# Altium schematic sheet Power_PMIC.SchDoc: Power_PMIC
size A3; CompanyName: STMicroelectronics; Organization: Microcontrollers Division; Address1: 12, Rue Jules HOROWITZ; Address2: 38019 Grenoble; Address3: FRANCE; SheetNumber: 5; SheetTotal: 7
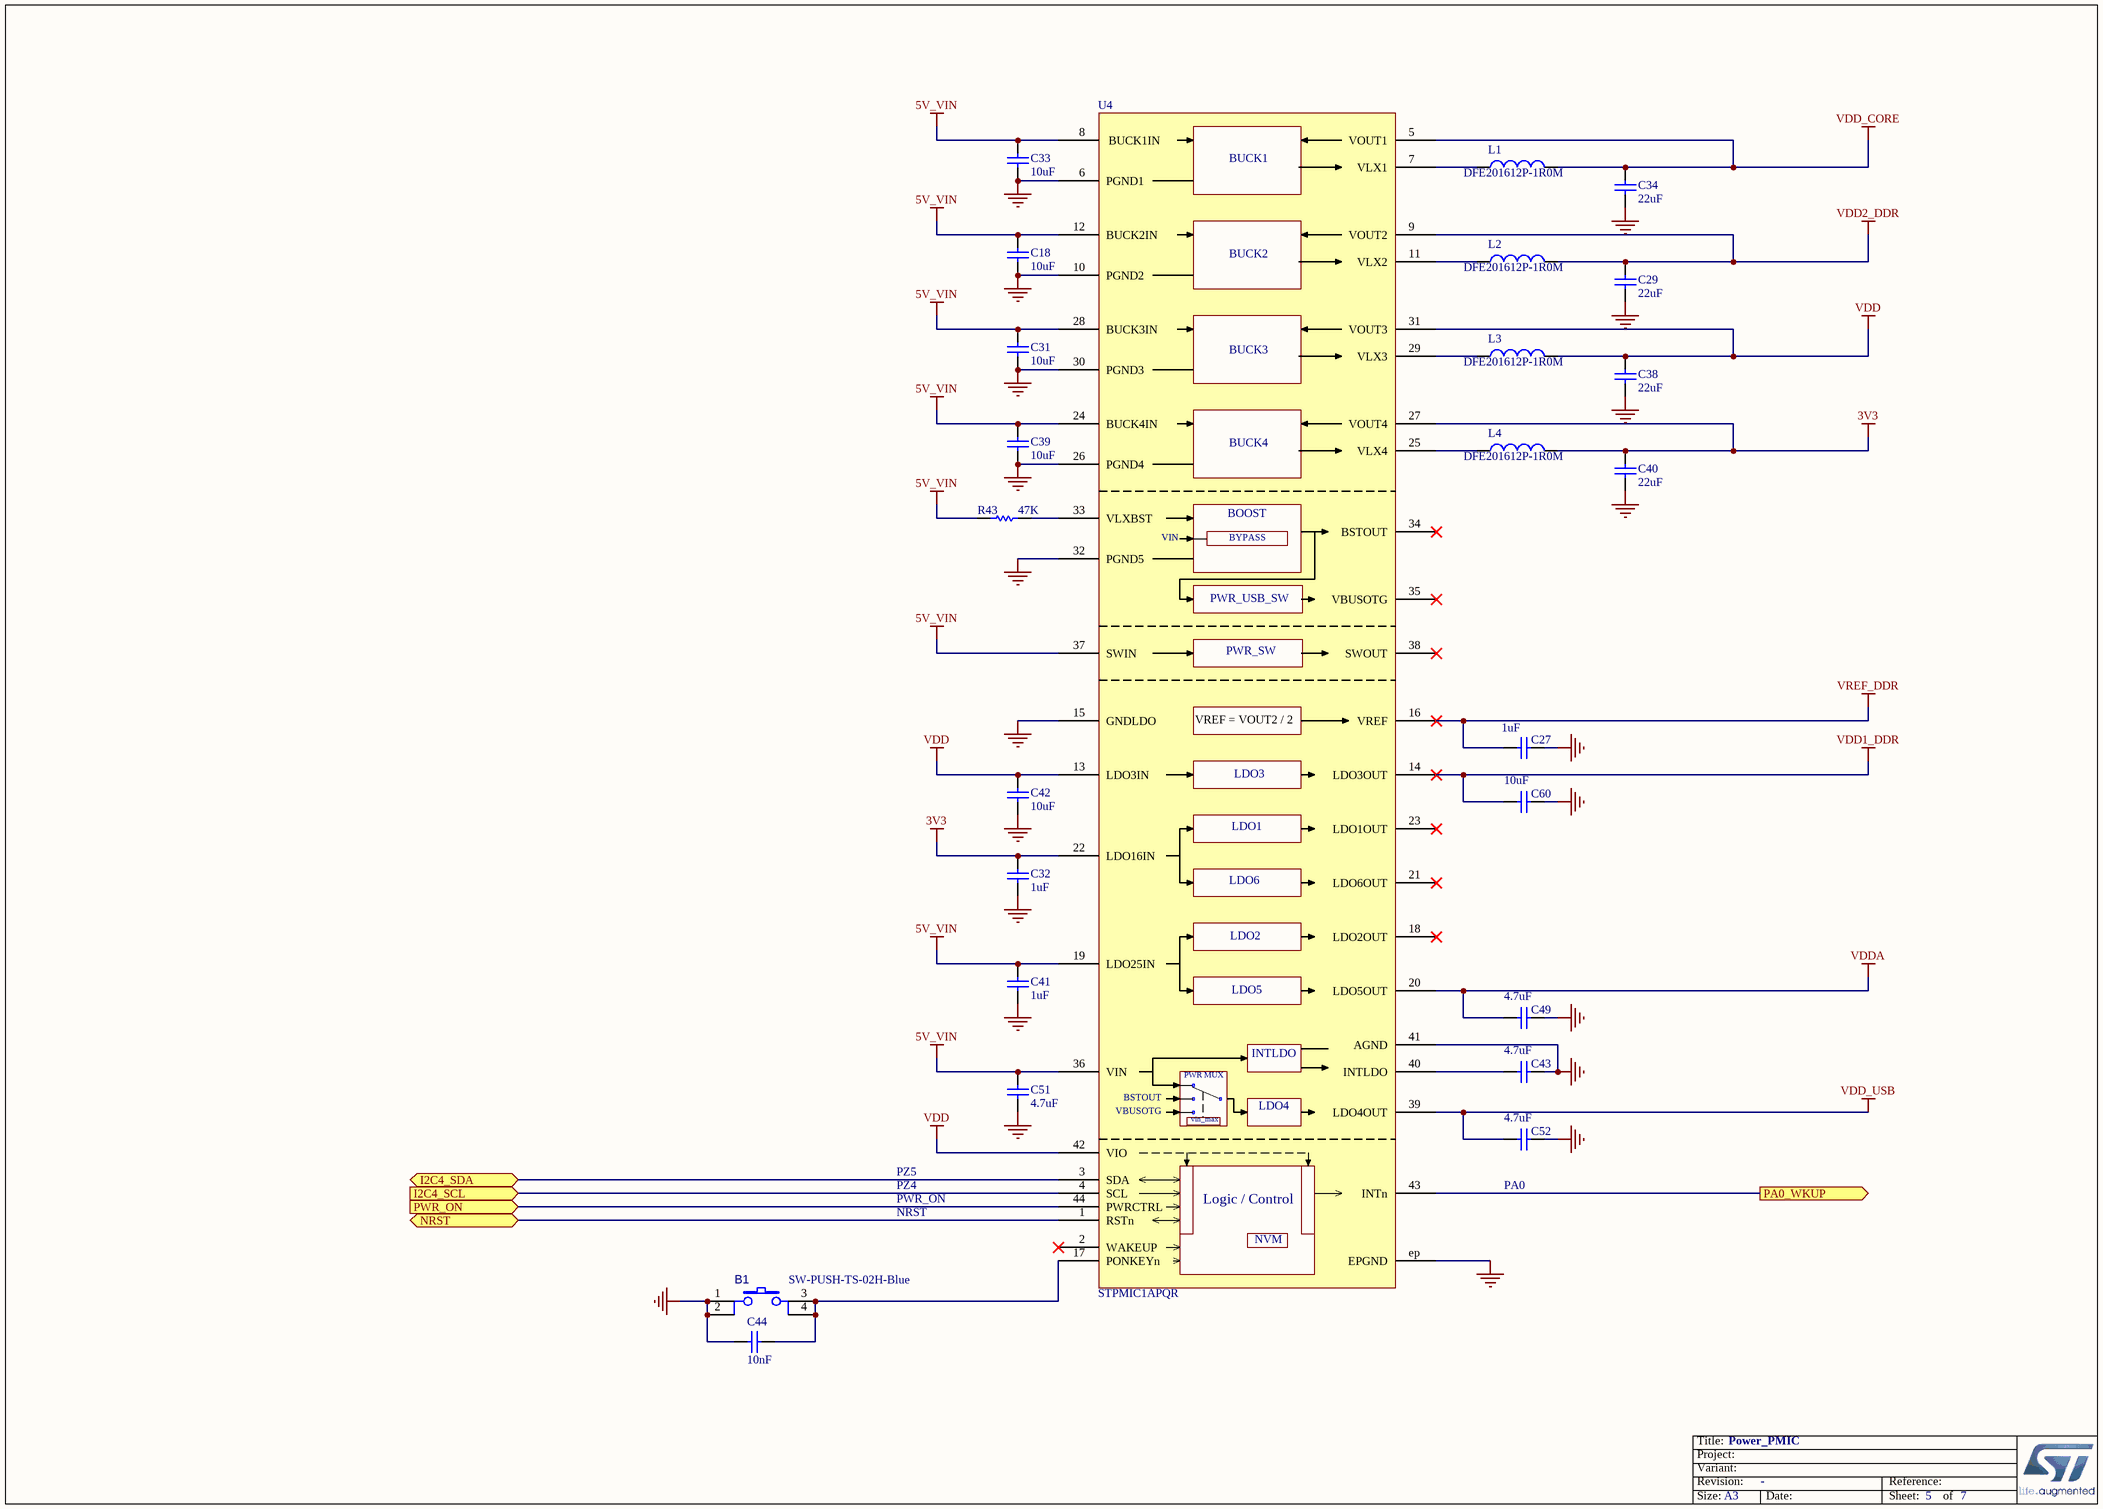
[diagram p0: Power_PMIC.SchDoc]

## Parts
B1  value SW-PUSH-TS-02H-Blue  [SWI_JIUBABA_C-TS-02H-2-5-B-V-T_R_BLUE]
C18  value 10uF  [C0603]
C27  value 1uF  [C0402]
C29  value 22uF  [C0603]
C31  value 10uF  [C0603]
C32  value 1uF  [C0402]
C33  value 10uF  [C0603]
C34  value 22uF  [C0603]
C38  value 22uF  [C0603]
C39  value 10uF  [C0603]
C40  value 22uF  [C0603]
C41  value 1uF  [C0402]
C42  value 10uF  [C0603]
C43  value 4.7uF  [C0402]
C44  value 10nF  [C0402]
C49  value 4.7uF  [C0402]
C51  value 4.7uF  [C0402]
C52  value 4.7uF  [C0402]
C60  value 10uF  [C0603]
L1  value DFE201612P-1R0M  [IND_MURATA_DFE201612P]
L2  value DFE201612P-1R0M  [IND_MURATA_DFE201612P]
L3  value DFE201612P-1R0M  [IND_MURATA_DFE201612P]
L4  value DFE201612P-1R0M  [IND_MURATA_DFE201612P]
R43  value 47K  [R0402]
U4  value STPMIC1APQR  [ICC_WFQFN44-EPAD_5X6_P040]

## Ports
I2C4_SCL (in), I2C4_SDA (bidir), NRST (bidir), PA0_WKUP (out), PWR_ON (in)

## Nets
3V3: C32.2 C40.2 L4.2 U4.22(LDO16IN) U4.27(VOUT4)
5V_VIN: C18.2 C31.2 C33.2 C39.2 C41.2 C51.1 R43.2 U4.8(BUCK1IN) U4.12(BUCK2IN) U4.19(LDO25IN) U4.24(BUCK4IN) U4.28(BUCK3IN) U4.36(VIN) U4.37(SWIN)
GND: B1.1 B1.2 C18.1 C27.1 C29.1 C31.1 C32.1 C33.1 C34.1 C38.1 C39.1 C40.1 C41.1 C42.1 C43.1 C44.1 C49.1 C51.2 C52.1 C60.1 U4.6(PGND1) U4.10(PGND2) U4.15(GNDLDO) U4.26(PGND4) U4.30(PGND3) U4.32(PGND5) U4.41(AGND) U4.ep(EPGND)
VDD: C38.2 C42.2 L3.2 U4.13(LDO3IN) U4.31(VOUT3) U4.42(VIO)
VDD1_DDR: C60.2 U4.14(LDO3OUT)
VDD2_DDR: C29.2 L2.2 U4.9(VOUT2)
VDD_CORE: C34.2 L1.2 U4.5(VOUT1)
VDD_USB: C52.2 U4.39(LDO4OUT)
VDDA: C49.2 U4.20(LDO5OUT)
VREF_DDR: C27.2 U4.16(VREF)
I2C4_SCL: U4.4(SCL) ; port I2C4_SCL
I2C4_SDA: U4.3(SDA) ; port I2C4_SDA
NRST: U4.1(RSTn) ; port NRST
PA0_WKUP: U4.43(INTn) ; port PA0_WKUP
PWR_ON: U4.44(PWRCTRL) ; port PWR_ON
NetB1_3: B1.3 B1.4 C44.2 U4.17(PONKEYn)
NetC43_2: C43.2 U4.40(INTLDO)
NetL1_1: L1.1 U4.7(VLX1)
NetL2_1: L2.1 U4.11(VLX2)
NetL3_1: L3.1 U4.29(VLX3)
NetL4_1: L4.1 U4.25(VLX4)
NetR43_1: R43.1 U4.33(VLXBST)

Not connected (* = marked no-connect by the designer): U4 2(WAKEUP)* 18(LDO2OUT)* 21(LDO6OUT)* 23(LDO1OUT)* 34(BSTOUT)* 35(VBUSOTG)* 38(SWOUT)*

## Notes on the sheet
- PZ5
- PZ4
- (near C52) PA0
- PWR_ON
- NRST

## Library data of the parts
B1 = MCD-00172: Switch HW SMD blue; Part_Type: Misc; Manufacturer_Part_Number: C-TS-02H-2.5-B-V-T/R BLUE; Manufacturer: JIUBABA; Provided_By: SUBCO
C18 C31 C33 C39 C42 C60 = MCD-00099: Capacitor, MLCC, 10uF, 10V, X5R, 10%, 0603, T=0,8mm; Manufacturer_Part_Number: GRM188R61A106KE69D; Manufacturer: MURATA; Provided_By: SUBCO; ECCN_US: EAR99; ECCN_EU: NEC
C27 C32 C41 = MCD-00095: Capacitor, MLCC, 1uF, 25V, X5R, 10%, 0402, T=0,5mm; Manufacturer_Part_Number: GRM155R61E105KA12; Manufacturer: MURATA; Alternate_Manufacturer_Part_Number: GRM155R60J105KE19; Provided_By: SUBCO; ECCN_US: EAR99; ECCN_EU: NEC
C29 C34 C38 C40 = MCD-00100: Capacitor, MLCC, 22uF, 6V3, X5R, 20%, 0603, T=0,8mm; Manufacturer_Part_Number: GRM188R60J226MEA0J; Manufacturer: MURATA; Provided_By: SUBCO; ECCN_US: EAR99; ECCN_EU: NEC
C43 C49 C51 C52 = MCD-01356: Capacitor, MLCC, 4.7uF, 6V3, X5R, 20%, 0402, T=0,5mm; Manufacturer_Part_Number: GRM155R60J475ME47; Manufacturer: MURATA; Alternate_Manufacturer_Part_Number: GRM155R60J475ME87; Provided_By: SUBCO; ECCN_US: EAR99; ECCN_EU: NEC
C44 = MCD-00011: Capacitor, MLCC, 10nF, 16V, X7R, 10%, 0402, T=0.5mm; Manufacturer_Part_Number: CC0402KRX7R7BB103; Manufacturer: YAGEO; Provided_By: SUBCO; ECCN_US: EAR99; ECCN_EU: NEC
L1-L4 = MCD-01491: Inductors 1.0uH 54mOhms3.3A +/-20% 2016; Manufacturer: MURATA; Provided_By: SUBCO
R43 = MCD-00063: Resistor,47K,0402,1%,1/16W; Manufacturer_Part_Number: RC0402FR-0747KL; Manufacturer: YAGEO; Provided_By: SUBCO; ECCN_US: EAR99; ECCN_EU: NEC
U4 = MCD-01650: ST PMIC:  4 step-down + 1 advanced boost SMPS, 6 LDOs, 2 pwr switches, DDR Vref, NVM option 'A' for IO@3.3V; Part_Type: IC; Manufacturer: STMICROELECTRONICS; BMS_Part_Number: 9177723; ECCN_US: EAR99; ECCN_EU: NEC; Provided_By: SUBCO with ST control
